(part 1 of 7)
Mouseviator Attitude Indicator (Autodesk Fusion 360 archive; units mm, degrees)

design "Mouseviator Attitude Indicator" references "Bezel BOXY LED and Glass MS33638C", "G1000/Steam C172 Panel Sketch", "Bezel LED and Glass MS33638C", "ULN2003 Stepper Driver v18", "Hall Effect Sensor SS494B", "microswitch 10T85", "28BYJ-48"
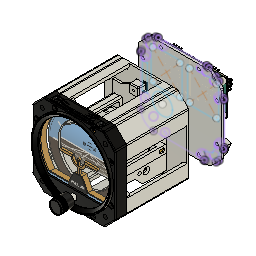
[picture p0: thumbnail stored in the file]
parameter "User Parameter" = 0 (= "Real is 85 but the way I did this makes it impractical")
parameter "MagRollDim" = 32
parameter "MagPitchDim" = 22
parameter "d63" = 5
parameter "d519" = 3
canvas "Canvas1"
canvas "Canvas2"
canvas "Canvas1" bodies "Standard Bezel"
canvas "Canvas1" bodies "Body1"
external_derived "Instrument Sketch" bodies "Body1", "Body2", "Standard Bezel", "Seal", "Top LED Holder"
derived_instance "DerivedInstance1"
joint "Assemble1"
derived_instance "DerivedInstance1"
derived_instance "DerivedInstance2"
derived_instance "DerivedInstance3"
derived_instance "DerivedInstance4"
derived_instance "DerivedInstance5"
derived_instance "DerivedInstance1"
derived_instance "DerivedInstance2"
external_derived "ExternalDerived1" bodies "Standard Bezel (1)"
move "Move3"
extrude "Extrude4" add of existing geometry to an object bodies "Standard Bezel"
delete_face "DeleteFace1"
delete_face "DeleteFace2"
sketch "Sketch1" plane through (0, -8.25, 0) normal (0, -1, 0) x axis (1, 0, 0)
  line L1 (46.051, -23.75) -> (-31.7968, -23.75)
  line L2 (29.1716, -41.2776) -> (-29.1716, -41.2776)
  arc A1 centre (36.96, 18.76) radius 2.5 clockwise from (34.5701, 19.4937) to (36.1415, 16.3978)
  arc A2 centre (0, 0) radius 39.6875 clockwise from (-34.4065, -19.781) to (-34.5701, -19.4937)
  arc A3 centre (36.96, -18.76) radius 2.5 clockwise from (36.1415, -16.3978) to (34.5701, -19.4937)
  arc A4 centre (0, 0) radius 39.6875 clockwise from (34.5701, -19.4937) to (34.4065, -19.781)
  arc A5 centre (18.76, -36.96) radius 2.5 clockwise from (19.4937, -34.5701) to (16.3978, -36.1415)
  arc A6 centre (0, 0) radius 39.6875 clockwise from (16.3978, -36.1415) to (16.0962, -36.2769)
  arc A7 centre (-18.76, -36.96) radius 2.5 clockwise from (-16.3978, -36.1415) to (-19.4937, -34.5701)
  arc A8 centre (0, 0) radius 39.6875 clockwise from (-19.4937, -34.5701) to (-19.781, -34.4065)
  arc A9 centre (-36.96, -18.76) radius 2.5 clockwise from (-34.5701, -19.4937) to (-36.1415, -16.3978)
  arc A10 centre (0, 0) radius 39.6875 clockwise from (-36.1415, -16.3978) to (-36.2769, -16.0962)
  arc A11 centre (-36.96, 18.76) radius 2.5 clockwise from (-36.1415, 16.3978) to (-34.5701, 19.4937)
  arc A12 centre (0, 0) radius 39.6875 clockwise from (-34.5701, 19.4937) to (-34.4065, 19.781)
  arc A13 centre (-18.76, 36.96) radius 2.5 clockwise from (-19.4937, 34.5701) to (-16.3978, 36.1415)
  arc A14 centre (0, 0) radius 39.6875 clockwise from (-16.3978, 36.1415) to (-16.0962, 36.2769)
  arc A15 centre (18.76, 36.96) radius 2.5 clockwise from (16.3978, 36.1415) to (19.4937, 34.5701)
  arc A16 centre (0, 0) radius 39.6875 clockwise from (19.4937, 34.5701) to (19.781, 34.4065)
  circle C1 centre (0, -29.75) radius 3
  arc A17 centre (0, 0) radius 39.6875 clockwise from (-16.3978, -36.1415) to (-19.4937, -34.5701)
  arc A18 centre (0, 0) radius 39.6875 clockwise from (19.4937, -34.5701) to (16.3978, -36.1415)
  arc A19 centre (-36.96, -18.76) radius 2.75 clockwise from (-34.4065, -19.781) to (-36.2769, -16.0962)
  arc A20 centre (36.96, -18.76) radius 2.75 clockwise from (36.2769, -16.0962) to (34.4065, -19.781)
  arc A21 centre (0, 0) radius 39.6875 clockwise from (36.2769, -16.0962) to (36.1415, -16.3978)
  arc A22 centre (18.76, -36.96) radius 2.75 clockwise from (19.781, -34.4065) to (16.0962, -36.2769)
  arc A23 centre (0, 0) radius 39.6875 clockwise from (19.781, -34.4065) to (19.4937, -34.5701)
  arc A24 centre (-18.76, -36.96) radius 2.75 clockwise from (-16.0962, -36.2769) to (-19.781, -34.4065)
  arc A25 centre (0, 0) radius 39.6875 clockwise from (-16.0962, -36.2769) to (-16.3978, -36.1415)
  arc A26 centre (-18.76, 36.96) radius 2.75 clockwise from (-19.781, 34.4065) to (-16.0962, 36.2769)
  arc A27 centre (0, 0) radius 39.6875 clockwise from (-19.781, 34.4065) to (-19.4937, 34.5701)
  arc A28 centre (-36.96, 18.76) radius 2.75 clockwise from (-36.2769, 16.0962) to (-34.4065, 19.781)
  arc A29 centre (0, 0) radius 39.6875 clockwise from (-36.2769, 16.0962) to (-36.1415, 16.3978)
  arc A30 centre (36.96, 18.76) radius 2.75 clockwise from (34.4065, 19.781) to (36.2769, 16.0962)
  arc A31 centre (0, 0) radius 39.6875 clockwise from (34.4065, 19.781) to (34.5701, 19.4937)
  arc A32 centre (0, 0) radius 39.6875 clockwise from (36.1415, 16.3978) to (36.2769, 16.0962)
  arc A33 centre (18.76, 36.96) radius 2.75 clockwise from (16.0962, 36.2769) to (19.781, 34.4065)
  arc A34 centre (0, 0) radius 39.6875 clockwise from (16.0962, 36.2769) to (16.3978, 36.1415)
  circle C2 centre (0, 0) radius 35.6721
  point P27 (-31.7968, -23.75)
  point P1 (0, 0)
  point P29 (0, -29.75)
  coincident A8 P27
  horizontal L1
  vertical P1 P29
  dimension "d1" distance P1 L1 = 23.75
  dimension "d2" diameter C1 = 6
  dimension "d3" distance L1 P29 = 6
extrude "Extrude1" add sketch "Sketch1" profile of L1 C1 C2 against normal blind 10.25 and against normal blind 0
work_plane "WorkPlane1" AlongDistance 60
sketch "Backing Plate" plane through (0, 62, 0) normal (0, 1, 0) x axis (1, 0, 0)
  line L1 (-1.5, 41.2776) -> (1.5, 41.2776)
  line L2 (-15, 0) -> (0, 0)
  line L3 (0, -15) -> (0, 0)
  line L4 (0, -15) -> (0, -22.5)
  line L5 (0, 15) -> (0, 22.5)
  line L6 (13.3564, 0) -> (0, 0)
  line L7 (-26.748, -34.183) -> (-33.4655, -27.4655)
  line L8 (-25.7359, -27.4655) -> (-33.4655, -27.4655)
  line L9 (-40.6918, 30.5858) -> (-30.5858, 40.6918)
  line L10 (-41.2776, -29.1716) -> (-41.2776, 29.1716)
  line L11 (-30.5858, -40.6918) -> (-40.6918, -30.5858)
  line L12 (-25.502, -41.2776) -> (-29.1716, -41.2776)
  line L13 (24.1231, -41.4655) -> (-24.1331, -41.4655)
  line L14 (29.1716, -41.2776) -> (25.492, -41.2776)
  line L15 (40.6918, -30.5858) -> (30.5858, -40.6918)
  line L16 (41.2776, 29.1716) -> (41.2776, -29.1716)
  line L17 (30.5858, 40.6918) -> (40.6918, 30.5858)
  line L18 (1.5, 41.2776) -> (29.1716, 41.2776)
  line L19 (1.5, 39.6216) -> (1.5, 41.2776)
  line L20 (-1.5, 41.2776) -> (-1.5, 39.6216)
  line L21 (-29.1716, 41.2776) -> (-1.5, 41.2776)
  line L22 (-15, 8.75) -> (-22.5, 8.75)
  line L23 (-15, -8.75) -> (-15, 8.75)
  line L24 (-22.5, -8.75) -> (-15, -8.75)
  line L25 (-22.5, 8.75) -> (-22.5, -8.75)
  line L26 (-15, -8.75) -> (-22.5, 8.75)
  line L27 (-22.5, -8.75) -> (-15, 8.75)
  line L28 (-15, 0) -> (-22.5, 0)
  line L29 (2.325, -29.875) -> (-2.325, -29.875)
  line L30 (2.325, -34.125) -> (2.325, -29.875)
  line L31 (-2.325, -34.125) -> (2.325, -34.125)
  line L32 (-2.325, -29.875) -> (-2.325, -34.125)
  line L33 (2.325, -34.125) -> (-2.325, -29.875)
  line L34 (-2.325, -34.125) -> (2.325, -29.875)
  line L35 (-2.3746, -28.5229) -> (-2.325, -29.875)
  line L36 (2.325, -29.875) -> (2.3746, -28.5229)
  line L37 (1.75, -27.875) -> (-1.75, -27.875)
  line L38 (-1.75, -29.125) -> (1.75, -29.125)
  circle C1 centre (0, 0) radius 5
  arc A1 centre (0, 0) radius 15 clockwise from (0, -15) to (-15, 0)
  arc A2 centre (0, 0) radius 22.5 clockwise from (0, -22.5) to (-22.5, 0)
  arc A3 centre (0, 0) radius 22.5 clockwise from (-22.5, 0) to (0, 22.5)
  arc A4 centre (0, 0) radius 15 clockwise from (-15, 0) to (0, 15)
  circle C2 centre (-33.4655, -27.4655) radius 1.4
  circle C3 centre (-26.748, -34.183) radius 1.4
  circle C4 centre (-31.4309, 31.4309) radius 2.159
  circle C5 centre (-31.4309, -31.4309) radius 2.159
  circle C6 centre (31.4309, 31.4309) radius 2.159
  circle C7 centre (31.4309, -31.4309) radius 2.159
  circle C8 centre (18.76, -36.96) radius 1.4
  circle C9 centre (36.96, 18.76) radius 1.4
  circle C10 centre (-18.76, 36.96) radius 1.4
  circle C11 centre (-36.96, -18.76) radius 1.4
  circle C12 centre (-18.76, -36.96) radius 1.4
  circle C13 centre (-36.96, 18.76) radius 1.4
  circle C14 centre (18.76, 36.96) radius 1.4
  circle C15 centre (36.96, -18.76) radius 1.4
  arc A5 centre (-39.2776, 29.1716) radius 2 clockwise from (-41.2776, 29.1716) to (-40.6918, 30.5858)
  arc A6 centre (-39.2776, -29.1716) radius 2 clockwise from (-40.6918, -30.5858) to (-41.2776, -29.1716)
  arc A7 centre (-29.1716, -39.2776) radius 2 clockwise from (-29.1716, -41.2776) to (-30.5858, -40.6918)
  arc A8 centre (-24.1331, -36.3855) radius 5.08 clockwise from (-24.1331, -41.4655) to (-25.502, -41.2776)
  arc A9 centre (24.1231, -36.3855) radius 5.08 clockwise from (25.492, -41.2776) to (24.1231, -41.4655)
  arc A10 centre (29.1716, -39.2776) radius 2 clockwise from (30.5858, -40.6918) to (29.1716, -41.2776)
  arc A11 centre (39.2776, -29.1716) radius 2 clockwise from (41.2776, -29.1716) to (40.6918, -30.5858)
  arc A12 centre (39.2776, 29.1716) radius 2 clockwise from (40.6918, 30.5858) to (41.2776, 29.1716)
  arc A13 centre (29.1716, 39.2776) radius 2 clockwise from (29.1716, 41.2776) to (30.5858, 40.6918)
  arc A14 centre (0, 0) radius 39.65 clockwise from (1.5, 39.6216) to (-1.5, 39.6216)
  arc A15 centre (-29.1716, 39.2776) radius 2 clockwise from (-30.5858, 40.6918) to (-29.1716, 41.2776)
  circle C16 centre (0, -28.5) radius 0.625
  circle C17 centre (-1.75, -28.5) radius 0.625
  circle C18 centre (1.75, -28.5) radius 0.625
  point P5 (0, -15)
  point P11 (0, 15)
  point P7 (0, -22.5)
  point P10 (0, 22.5)
  point P8 (0, 0)
  point P13 (0, 0)
  point P15 (-33.4655, -27.4655)
  point P17 (-33.4655, -27.4655)
  point P16 (-26.748, -34.183)
  point P18 (-26.748, -34.183)
  point P65 (1.5, 41.2776)
  point P75 (1.5, 41.2776)
  point P71 (-1.5, 41.2776)
  point P76 (-1.5, 41.2776)
  point P81 (-18.75, 0)
  point P2 (0, 0)
  point P12 (0, 0)
  point P1 (0, 0)
  point P86 (0, -32)
  point P87 (0, -28.5)
  point P90 (-2.3746, -28.5229)
  point P91 (2.3746, -28.5229)
  point P92 (-1.75, -27.875)
  point P93 (1.75, -27.875)
  point P94 (1.75, -29.125)
  point P95 (-1.75, -29.125)
  point P79 (-15, -8.75)
  point P80 (-22.5, -8.75)
  point P78 (-15, 8.75)
  point P6 (0, 0)
  point P83 (2.325, -29.875)
  point P84 (2.325, -34.125)
  point P82 (-2.325, -29.875)
  parallel L3 L4
  symmetric P5 L2 P11
  symmetric A1 L2 A4
  symmetric L2 P7 P10
  symmetric L2 A2 A3
  coincident P8 P13
  horizontal L6
  horizontal L8
  coincident P15 P17
  coincident P16 P18
  coincident P65 P75
  coincident P71 P76
  horizontal L22
  perpendicular L22 L23
  parallel L22 L24
  parallel L23 L25
  coincident L26 P81
  coincident L27 P81
  parallel L2 L28
  midpoint P81 L28
  coincident P2 P12
  coincident P1 P8
  horizontal L29
  perpendicular L29 L30
  parallel L29 L31
  parallel L30 L32
  coincident L33 P86
  coincident L34 P86
  vertical P8 P86
  vertical P86 P87
  coincident C17 P90
  tangent C17 L35
  coincident C18 P91
  tangent C18 L36
  coincident C17 P92
  coincident C18 P93
  tangent C18 L37
  coincident C18 P94
  coincident C17 P95
  tangent C17 L38
  dimension "d9" diameter C1 = 10
  dimension "d92" angle L2 L3 = 90
  dimension "d93" radius A1 = 15
  dimension "d94" = 7.5
  dimension "d95" angle L2 L6 = 180
  dimension "d182" diameter C2 = 2.8
  dimension "d183" diameter C3 = 2.8 (= "d182")
  dimension "d184" angle L7 L8 = 45
  dimension "d185" distance P17 P18 = 9.5
  dimension "d363" distance P79 P80 = 7.5
  dimension "d364" distance P78 P79 = 17.5
  dimension "d437" distance P6 P86 = 32 (= "MagRollDim")
  dimension "d438" distance P83 P84 = 4.25
  dimension "d439" distance P82 P83 = 4.65
  dimension "d442" distance P86 P87 = 3.5
  dimension "d443" diameter C16 = 1.25
  dimension "d446" R-Pattern1-uDistance = 1.75
  dimension "d447" R-Pattern1-vDistance = 0
extrude "Extrude1" new body sketch "Backing Plate" profile of L1 C1 A1 A2 L4 A3 L5 A4 C2 C3 L7 C4 C5 C6 C7 C8 C9 C10 C11 C12 C13 C14 C15 L9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 along normal blind 2
component_insert "Component Insert1"
joint "Assemble1" alignAngle 0 alignOffsetX 0 alignOffsetY 0 alignOffsetZ 0
work_plane "WorkPlane1" AlongDistance -1.5
sketch "Square with wall profiles" plane through (0, 55.28, 0) normal (0, -1, 0) x axis (1, 0, 0)
  line L1 (23, -27) -> (23, 27)
  line L2 (26, -27) -> (26, 27)
  line L3 (-26, 27) -> (26, 27)
  line L4 (-26, -27) -> (-26, 27)
  line L5 (26, -27) -> (-26, -27)
  line L6 (26, 27) -> (26, -27)
  line L7 (-26, -27) -> (26, 27)
  line L8 (26, -27) -> (-26, 27)
  line L9 (0, 16.6092) -> (0, 0)
  line L10 (-23, -27) -> (-23, 27)
  line L11 (-23, 14.5) -> (-26, 14.5)
  line L12 (-23, -14.5) -> (-26, -14.5)
  line L13 (-21.5, -9) -> (-13.5, -9)
  line L14 (-21.5, 9) -> (-21.5, -9)
  line L15 (-13.5, 9) -> (-21.5, 9)
  line L16 (-13.5, -9) -> (-13.5, 9)
  line L17 (-21.5, 9) -> (-13.5, -9)
  line L18 (-13.5, 9) -> (-21.5, -9)
  line L19 (-1.6591, 1.46) -> (1.6591, 1.46)
  line L20 (1.6591, -1.46) -> (-1.6591, -1.46)
  line L21 (-1.7896, 1.76) -> (1.7896, 1.76)
  line L22 (1.7896, -1.76) -> (-1.7896, -1.76)
  line L23 (0, 35.4451) -> (-7.5188, 31.1041)
  line L24 (0, 35.4451) -> (7.5188, 31.1041)
  line L25 (2.75, 34.75) -> (-2.75, 34.75)
  line L26 (2.75, 29.25) -> (2.75, 34.75)
  line L27 (-2.75, 29.25) -> (2.75, 29.25)
  line L28 (-2.75, 34.75) -> (-2.75, 29.25)
  line L29 (2.75, 29.25) -> (-2.75, 34.75)
  line L30 (-2.75, 29.25) -> (2.75, 34.75)
  line L31 (-4.75, 27.25) -> (4.75, 27.25)
  line L32 (-4.75, 36.75) -> (-4.75, 27.25)
  line L33 (4.75, 36.75) -> (-4.75, 36.75)
  line L34 (4.75, 27.25) -> (4.75, 36.75)
  arc A1 centre (0, 0) radius 2.21 clockwise from (-1.6591, -1.46) to (-1.6591, 1.46)
  arc A2 centre (0, 0) radius 2.21 clockwise from (1.6591, 1.46) to (1.6591, -1.46)
  arc A3 centre (0, 0) radius 2.51 clockwise from (-1.7896, -1.76) to (-1.7896, 1.76)
  arc A4 centre (0, 0) radius 2.51 clockwise from (1.7896, 1.76) to (1.7896, -1.76)
  circle C1 centre (0, 0) radius 32
  circle C2 centre (0, 0) radius 6.25
  circle C3 centre (0, 32) radius 1
  point P8 (0, 0)
  point P4 (26, 27)
  point P2 (23, 27)
  point P1 (0, 0)
  point P9 (0, 0)
  point P11 (-23, 27)
  point P3 (23, -27)
  point P12 (-23, -27)
  point P13 (-26, 14.5)
  point P14 (-23, 14.5)
  point P15 (-26, -14.5)
  point P16 (-23, -14.5)
  point P21 (-17.5, 0)
  point P34 (-7.5188, 31.1041)
  point P33 (0, 0)
  point P35 (0, 35.4451)
  point P36 (7.5188, 31.1041)
  point P37 (0, 35.4451)
  point P43 (0, 32)
  point P48 (0, 32)
  point P7 (26, -27)
  point P19 (-21.5, 9)
  point P20 (-13.5, 9)
  point P18 (-21.5, -9)
  point P41 (2.75, 29.25)
  point P42 (-2.75, 29.25)
  point P40 (2.75, 34.75)
  vertical L1
  parallel L1 L2
  horizontal L3
  perpendicular L3 L4
  parallel L3 L5
  parallel L4 L6
  coincident L7 P8
  coincident L8 P8
  coincident L2 P4
  coincident P2 L3
  coincident P1 P8
  coincident P8 P9
  perpendicular L3 L9
  symmetric P2 L9 P11
  symmetric P3 L9 P12
  coincident L4 P13
  coincident L10 P14
  perpendicular L10 L11
  coincident L4 P15
  coincident L10 P16
  perpendicular L10 L12
  horizontal L13
  perpendicular L13 L14
  parallel L13 L15
  parallel L14 L16
  coincident L17 P21
  coincident L18 P21
  concentric A1 C1
  coincident C1 P34
  vertical P33 P35
  symmetric L9 P34 P36
  symmetric L9 P35 P37
  horizontal P21 P33
  concentric C1 C2
  coincident P3 L5
  horizontal L25
  perpendicular L25 L26
  parallel L25 L27
  parallel L26 L28
  coincident L29 P43
  coincident L30 P43
  coincident L9 P43
  coincident P43 P48
  dimension "d22" distance L1 L2 = 3
  dimension "d60" distance P1 L1 = 23
  dimension "d64" distance P4 P7 = 54
  dimension "d86" distance L3 L11 = 12.5
  dimension "d87" distance L5 L12 = 12.5 (= "d86")
  dimension "d90" distance P19 P20 = 8
  dimension "d91" distance P18 P19 = 18
  dimension "d96" distance P8 P21 = 17.5
  dimension "d171" = 0.3
  dimension "d176" diameter C1 = 64
  dimension "d177" angle L3 L23 = 30
  dimension "d373" diameter C2 = 12.5
  dimension "d425" distance P41 P42 = 5.5
  dimension "d426" distance P40 P41 = 5.5
  dimension "d427" distance P33 P43 = 32 (= "MagRollDim")
  dimension "d428" = -2
  dimension "d511" diameter C3 = 2
extrude "Extrude1" new body sketch "Square with wall profiles" profile of L1 L2 L3 L4 L5 L6 L10 L11 L12 L13 L14 L15 L16 A4 L21 A3 L22 C1 C2 L25 L26 L27 L28 L31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 against normal blind 2
extrude "Extrude13" add sketch "Square with wall profiles" profile of C1 L25 L26 L27 L28 L31 L32 L33 L34 along normal blind 3
extrude "Extrude14" sketch "Square with wall profiles" profile of C1 L25 L26 L27 L28 L31 L32 L33 L34 C3 blind 2
extrude "Extrude11" add sketch "Square with wall profiles" profile of A4 L21 A3 L22 C2 against normal blind 5
extrude "Extrude2" add sketch "Square with wall profiles" profile of L1 L2 L3 L5 L6 C1 along normal blind 30
sketch "Stepper and Microswitch mounting" plane through (23, 0, 0) normal (-1, 0, 0) x axis (0, -1, 0)
  line L1 (-25.28, 27) -> (-25.28, -27)
  line L2 (-55.28, -27) -> (-55.28, 27)
  line L3 (-55.28, 27) -> (-25.28, 27)
  line L4 (-35.1539, 6.3901) -> (-44.28, 0)
  line L5 (-43.6816, -0.8547) -> (-44.28, 0)
  line L6 (-27.6437, 0) -> (-44.28, 0)
  line L7 (-44.9981, 20.449) -> (-35.1539, 6.3901)
  line L8 (-52.78, 15) -> (-44.9981, 20.449)
  line L9 (-25.28, -27) -> (-55.28, -27)
  line L10 (-46.2143, 5.3599) -> (-32.6739, 14.8409)
  line L11 (-55.28, -27) -> (-55.28, 27)
  circle C1 centre (-44.28, 0) radius 5
  circle C2 centre (-44.9981, 20.449) radius 1.4
  circle C3 centre (-52.78, 15) radius 1.4
  circle C4 centre (-44.9981, -20.449) radius 1.4
  circle C5 centre (-52.78, -15) radius 1.4
  circle C6 centre (-48.889, 17.7245) radius 1.6
  circle C7 centre (-48.889, -17.7245) radius 1.6
  circle C8 centre (-30.1171, 16.6312) radius 1.6
  circle C9 centre (-30.1171, -16.6312) radius 1.6
  point P5 (-44.28, 0)
  point P6 (-55.28, 0)
  point P9 (-44.28, 0)
  point P11 (-44.28, 0)
  point P14 (-44.9981, 20.449)
  point P15 (-44.9981, 20.449)
  point P16 (-44.9981, 20.449)
  point P17 (-52.78, 15)
  point P18 (-52.78, 15)
  point P22 (-48.889, 17.7245)
  point P26 (-30.1171, 16.6312)
  point P10 (-35.1539, 6.3901)
  horizontal P5 P6
  coincident P5 P9
  coincident P5 P11
  perpendicular L4 L5
  horizontal L6
  perpendicular L4 L7
  coincident P14 P15
  coincident P15 P16
  perpendicular L7 L8
  coincident P17 P18
  equal C2 C3
  symmetric L6 C2 C4
  symmetric L6 C3 C5
  midpoint L8 P22
  symmetric L6 C6 C7
  perpendicular L7 L10
  coincident L10 P26
  symmetric L6 C8 C9
  dimension "d19" diameter C1 = 10
  dimension "d27" distance P5 L2 = 11
  dimension "d111" angle L4 L6 = 35 (= "PitchTravelDeg / 2")
  dimension "d118" distance P10 P14 = 17.1627
  dimension "d119" distance P9 P10 = 11.1409
  dimension "d121" diameter C2 = 2.8
  dimension "d122" distance P16 P17 = 9.5
  dimension "d386" distance P5 P18 = 15
  dimension "d387" distance P6 P18 = 2.5
  dimension "d420" diameter C6 = 3.2
  dimension "d421" diameter C8 = 3.2
  dimension "d422" distance L4 L10 = 5.5
  dimension "d424" distance L7 P26 = 10
extrude "Extrude3" cut sketch "Stepper and Microswitch mounting" profile of C1 C8 C9 to an object
component_insert "Component Insert2"
joint "Assemble2" alignAngle 90 alignOffsetX 0 alignOffsetY 0 alignOffsetZ 0
work_plane "WorkPlane1" AlongDistance 1
sketch "Right Arm" plane through (34.12, 54.78, 0) normal (1, 0, 0) x axis (0, 1, 0)
  line L1 (-47.5, -4) -> (-5.5, -4)
  line L2 (-47.5, 4) -> (-47.5, -4)
  line L3 (-5.5, 4) -> (-47.5, 4)
  line L4 (-5.5, -4) -> (-5.5, 4)
  line L5 (-47.5, 4) -> (-5.5, -4)
  line L6 (-5.5, 4) -> (-47.5, -4)
  line L7 (-8.8409, -1.46) -> (-12.1591, -1.46)
  line L8 (-12.1591, 1.46) -> (-8.8409, 1.46)
  line L9 (-8.7104, -1.76) -> (-12.2896, -1.76)
  line L10 (-12.2896, 1.76) -> (-8.7104, 1.76)
  arc A1 centre (-10.5, 0) radius 2.21 clockwise from (-8.8409, 1.46) to (-8.8409, -1.46)
  arc A2 centre (-10.5, 0) radius 2.21 clockwise from (-12.1591, -1.46) to (-12.1591, 1.46)
  circle C1 centre (-10.5, 0) radius 5
  arc A3 centre (-10.5, 0) radius 2.51 clockwise from (-8.7104, 1.76) to (-8.7104, -1.76)
  arc A4 centre (-10.5, 0) radius 2.51 clockwise from (-12.2896, -1.76) to (-12.2896, 1.76)
  point P6 (-26.5, 0)
  point P1 (0, 0)
  point P4 (-47.5, 4)
  point P5 (-5.5, 4)
  point P10 (-10.5, 0)
  point P2 (-5.5, -4)
  horizontal L1
  perpendicular L1 L2
  parallel L1 L3
  parallel L2 L4
  coincident L5 P6
  coincident L6 P6
  midpoint L6 P6
  horizontal P1 P6
  concentric A1 C1
  dimension "d61" distance P4 P5 = 42
  dimension "d160" distance L4 P10 = 5
  dimension "d161" distance P2 P5 = 8
  dimension "d392" = 0.3
  dimension "d423" diameter C1 = 10
extrude "Extrude1" new body sketch "Right Arm" profile of L1 L2 L3 L4 C1 L9 A4 L10 A3 against normal blind 2.5
mirror "Mirror1" mirrorStitchTolerance 0.1
work_axis "WorkAxis1"
work_plane "WorkPlane2" AlongDistance 0
sketch "Sketch2" plane through (0, 0, 0) normal (1, 0, 0) x axis (0, 1, 0)
  line L1 (7.28, 4) -> (7.28, -4)
  line L2 (14.9269, 20.8421) -> (13.2961, 22)
  line L3 (8.28, 0) -> (6.28, 0)
  line L4 (14.9269, -20.8421) -> (13.2961, -22)
  line L5 (57.28, 31.6455) -> (57.28, 27)
  line L6 (57.28, 31.6455) -> (57.28, 27)
  arc A1 centre (44.28, 0) radius 38 clockwise from (6.28, 0) to (13.2961, 22)
  arc A2 centre (44.28, 0) radius 36 clockwise from (8.28, 0) to (14.9269, 20.8421)
  arc A3 centre (44.28, 0) radius 38 clockwise from (13.2961, -22) to (6.28, 0)
  arc A4 centre (44.28, 0) radius 36 clockwise from (14.9269, -20.8421) to (8.28, 0)
  point P2 (44.28, 0)
  point P4 (6.28, 0)
  point P1 (0, 0)
  point P3 (13.2961, 22)
  point P11 (13.2961, -22)
  point P12 (6.28, 0)
  point P8 (8.28, 0)
  point P15 (8.28, 0)
  point P9 (14.9269, 20.8421)
  point P13 (14.9269, -20.8421)
  point P14 (44.28, 0)
  point P16 (44.28, 0)
  point P6 (7.28, 4)
  horizontal P2 P4
  horizontal P1 P4
  perpendicular L1 L3
  symmetric P3 L3 P11
  symmetric P4 L3 P12
  symmetric A1 L3 A3
  symmetric P8 L3 P15
  symmetric P9 L3 P13
  symmetric A2 L3 A4
  coincident P14 P16
  dimension "d38" = -2
  dimension "d140" distance P3 P6 = 18
  dimension "d141" distance L1 P15 = 1
extrude "Extrude2" add sketch "Sketch2" profile of A1 A2 L2 A3 L4 A4 distance 32.5
work_plane "WorkPlane1" AlongDistance 0.5
sketch "Sketch1" plane through (0, 2.5, 0) normal (0, 1, 0) x axis (1, 0, 0)
  circle C1 centre (0, 0) radius 37.25
  circle C2 centre (0, 0) radius 27.6721
  circle C3 centre (0, 0) radius 35.6721
  point P1 (0, 0)
  point P2 (0, 0)
  point P3 (0, 0)
  coincident P1 P2
  coincident P1 P3
  dimension "d504" diameter C1 = 74.5
  dimension "d528" distance C2 C3 = 8
extrude "Extrude1" new body sketch "Sketch1" profile of C1 C2 along normal blind 2
sketch "Sketch3" plane through (0, 0, 0) normal (0, 1, 0) x axis (-1, 0, 0)
  curve K1 (32.5, 0) -> (-32.5, 0)
  curve K2 (0, 17.7833) -> (0, -17.7833)
  line L1 (32.5, 22) -> (-32.5, 22)
  line L2 (-32.5, -22) -> (32.5, -22)
  line L3 (-32.5, -22) -> (-32.5, 22)
  line L4 (32.5, 22) -> (-32.5, 22)
  line L5 (32.5, 22) -> (32.5, -22)
  line L6 (34.12, 4) -> (34.12, -4)
  line L7 (31.62, 4) -> (34.12, 4)
  line L8 (31.62, -4) -> (31.62, 4)
  line L9 (34.12, -4) -> (31.62, -4)
  line L10 (-34.12, -4) -> (-34.12, 4)
  line L11 (-31.62, -4) -> (-34.12, -4)
  line L12 (-31.62, 4) -> (-31.62, -4)
  line L13 (-34.12, 4) -> (-31.62, 4)
  closed curve K3 centre (0, 0)
  point P3 (-32.5, 0)
  point P4 (32.5, 0)
  point P5 (0, -17.7833)
  point P6 (0, 17.7833)
  point P2 (0, 0)
  point P7 (0, 0)
  coincident K3 P3
  coincident K3 P4
  coincident K3 P5
  coincident K3 P6
  horizontal K1
  coincident P2 P7
extrude "Extrude3" cut sketch "Sketch3" profile of K3 L1 L2 L3 L4 L5 L7 L9 L11 L13 along normal blind 20
sketch "Sketch3" plane through (0, 0, 0) normal (1, 0, 0) x axis (0, 1, 0)
  line L1 (22.8033, 27) -> (24.0483, 25.4348)
  line L2 (42.7383, 0) -> (44.28, 0)
  line L3 (28.8507, 0) -> (42.7383, 0)
  line L4 (22.8033, -27) -> (24.0483, -25.4348)
  arc A1 centre (44.28, 0) radius 34.5 clockwise from (9.78, 0) to (22.8033, 27)
  arc A2 centre (44.28, 0) radius 32.5 clockwise from (11.78, 0) to (24.0483, 25.4348)
  arc A3 centre (44.28, 0) radius 38 clockwise from (6.4911, -4) to (6.4911, 4)
  arc A4 centre (44.28, 0) radius 34.5 clockwise from (22.8033, -27) to (9.78, 0)
  arc A5 centre (44.28, 0) radius 32.5 clockwise from (24.0483, -25.4348) to (11.78, 0)
  point P1 (0, 0)
  point P4 (9.78, 0)
  point P2 (44.28, 0)
  point P15 (6.28, 0)
  point P8 (44.28, 0)
  point P16 (44.28, 0)
  point P3 (22.8033, 27)
  point P20 (22.8033, -27)
  point P21 (9.78, 0)
  point P6 (24.0483, 25.4348)
  point P22 (24.0483, -25.4348)
  point P7 (11.78, 0)
  point P24 (11.78, 0)
  horizontal P1 P4
  horizontal P2 P4
  midpoint A3 P15
  coincident P2 P8
  coincident P2 P16
  horizontal L2
  parallel L2 L3
  symmetric P3 L3 P20
  symmetric P4 L3 P21
  symmetric A1 L3 A4
  symmetric P6 L3 P22
  symmetric A2 L3 A5
  symmetric P7 L3 P24
  dimension "d53" = -2
  dimension "d68" distance P1 P3 = 27
  dimension "d331" distance P4 P15 = 3.5 (= "2 mm + 1.5 mm")
extrude "Extrude4" new body sketch "Sketch3" profile of A1 A2 L1 distance 30
sketch "Sketch4" plane through (-3.75, 0, 0) normal (0, 1, 0) x axis (1, 0, 0)
  line L1 (33.75, 27) -> (33.75, -27)
  line L2 (-26.25, -27) -> (33.75, -27)
  line L3 (-26.25, -27) -> (-26.25, 27)
  curve K1 (33.75, 0) -> (-26.25, 0)
  curve K2 (3.75, 27) -> (3.75, -27)
  line L4 (33.75, 27) -> (-26.25, 27)
  closed curve K3 centre (3.75, 0)
  point P8 (-26.25, 0)
  point P9 (33.75, 0)
  point P10 (3.75, -27)
  point P11 (3.75, 27)
  point P6 (3.75, 0)
  point P7 (3.75, 0)
  coincident K3 P8
  coincident K3 P9
  coincident K3 P10
  coincident K3 P11
  coincident P6 P7
  perpendicular L1 K1
  coincident L2 P10
extrude "Extrude5" cut sketch "Sketch4" profile of L1 L2 L3 K3 along normal blind 50
as_built_joint "As-built1" OffsetX 0 OffsetY 0 OffsetZ 0 AngleZ 0 AngleMinimum -35 (= "-( PitchTravelDeg / 2 )") AngleMaximum 35 (= "( PitchTravelDeg / 2 )")
as_built_joint "As-built1" OffsetX 0 OffsetY 0 OffsetZ 0 AngleZ 0 AngleMinimum -180 AngleMaximum 180 RotateRest 0
ground "Ground1"
sketch "Sketch5" plane through (0, 25.28, 0) normal (0, -1, 0) x axis (1, 0, 0)
  line L1 (26, 27) -> (26, -27)
  line L2 (23, 27) -> (26, 27)
  line L3 (23, -27) -> (23, 27)
  line L4 (26, -27) -> (23, -27)
  line L5 (26, 19) -> (23, 19)
  line L6 (26, -19) -> (23, -19)
  point P6 (23, 19)
  point P7 (26, 19)
  point P8 (23, -19)
  point P9 (26, -19)
  coincident L3 P6
  coincident L1 P7
  perpendicular L1 L5
  coincident L3 P8
  coincident L1 P9
  perpendicular L1 L6
  dimension "d145" distance L4 L6 = 8 (= "d146")
  dimension "d146" distance L2 L5 = 8
extrude "Extrude6" add sketch "Sketch5" profile of L1 L3 L5 L6 to an object
extrude "Extrude7" add sketch "Square with wall profiles" profile of L4 L10 L11 L12 to an object
sketch "Left Arm" plane through (-34.12, 0, 0) normal (-1, 0, 0) x axis (0, -1, 0)
  line L1 (-49.28, 4) -> (-7.28, 4)
  line L2 (-49.28, -4) -> (-49.28, 4)
  line L3 (-7.28, -4) -> (-49.28, -4)
  line L4 (-7.28, 4) -> (-7.28, -4)
  circle C1 centre (-44.28, 0) radius 1.5
  point P6 (-44.28, 0)
  point P7 (-44.28, 0)
  coincident P6 P7
  dimension "d97" diameter C1 = 3
extrude "Extrude4" cut sketch "Left Arm" profile of C1 to an object
sketch "Sketch5" plane through (34.12, 0, 0) normal (1, 0, 0) x axis (0, 1, 0)
  line L1 (7.28, 4) -> (49.28, 4)
  line L2 (7.28, -4) -> (7.28, 4)
  line L3 (49.28, -4) -> (7.28, -4)
  line L4 (49.28, 4) -> (49.28, -4)
  line L5 (45.9391, -1.46) -> (42.6209, -1.46)
  line L6 (42.6209, 1.46) -> (45.9391, 1.46)
  line L7 (42.5115, 1.71) -> (46.0485, 1.71)
  line L8 (46.0485, -1.71) -> (42.5115, -1.71)
  arc A1 centre (44.28, 0) radius 2.21 clockwise from (45.9391, 1.46) to (45.9391, -1.46)
  arc A2 centre (44.28, 0) radius 2.21 clockwise from (42.6209, -1.46) to (42.6209, 1.46)
  arc A3 centre (44.28, 0) radius 2.46 clockwise from (42.5115, -1.71) to (42.5115, 1.71)
  arc A4 centre (44.28, 0) radius 2.46 clockwise from (46.0485, 1.71) to (46.0485, -1.71)
  dimension "d102" = 0.25
extrude "Extrude5" cut sketch "Sketch5" profile of A4 L7 A3 L8 to an object
sketch "Sketch1" plane through (0, 2, 0) normal (0, 1, 0) x axis (-1, 0, 0)
  line L1 (-1.35, -41.3) -> (-1.35, -39.627)
  line L2 (1.35, -41.3) -> (-1.35, -41.3)
  line L3 (1.35, -39.627) -> (1.35, -41.3)
  line L4 (-3.543, 32.597) -> (-3.543, 36.4783)
  line L5 (-2.0322, 27.1385) -> (-3.543, 32.597)
  line L6 (-0.9183, 27.1385) -> (-2.0322, 27.1385)
  line L7 (-0.9183, 36.6385) -> (-0.9183, 27.1385)
  line L8 (0, 10.54) -> (0, 0)
  line L9 (3.543, 32.597) -> (3.543, 36.4783)
  line L10 (2.0322, 27.1385) -> (3.543, 32.597)
  line L11 (0.9183, 27.1385) -> (2.0322, 27.1385)
  line L12 (0.9183, 36.6385) -> (0.9183, 27.1385)
  line L13 (-40.6918, 30.5858) -> (-30.5858, 40.6918)
  line L14 (-41.2776, -29.1716) -> (-41.2776, 29.1716)
  line L15 (-30.5858, -40.6918) -> (-40.6918, -30.5858)
  line L16 (-1.5, -41.2776) -> (-29.1716, -41.2776)
  line L17 (-1.5, -39.6216) -> (-1.5, -41.2776)
  line L18 (1.5, -41.2776) -> (1.5, -39.6216)
  line L19 (29.1716, -41.2776) -> (1.5, -41.2776)
  line L20 (40.6918, -30.5858) -> (30.5858, -40.6918)
  line L21 (41.2776, 29.1716) -> (41.2776, -29.1716)
  line L22 (30.5858, 40.6918) -> (40.6918, 30.5858)
  line L23 (25.502, 41.2776) -> (29.1716, 41.2776)
  line L24 (-24.1231, 41.4655) -> (24.1331, 41.4655)
  line L25 (-29.1716, 41.2776) -> (-25.492, 41.2776)
  circle C1 centre (0, 0) radius 36.65
  arc A1 centre (0, 0) radius 39.65 clockwise from (-1.35, -39.627) to (1.35, -39.627)
  arc A2 centre (-39.2776, 29.1716) radius 2 clockwise from (-41.2776, 29.1716) to (-40.6918, 30.5858)
  arc A3 centre (-39.2776, -29.1716) radius 2 clockwise from (-40.6918, -30.5858) to (-41.2776, -29.1716)
  arc A4 centre (-29.1716, -39.2776) radius 2 clockwise from (-29.1716, -41.2776) to (-30.5858, -40.6918)
  arc A5 centre (0, 0) radius 39.65 clockwise from (-1.5, -39.6216) to (1.5, -39.6216)
  arc A6 centre (29.1716, -39.2776) radius 2 clockwise from (30.5858, -40.6918) to (29.1716, -41.2776)
  arc A7 centre (39.2776, -29.1716) radius 2 clockwise from (41.2776, -29.1716) to (40.6918, -30.5858)
  arc A8 centre (39.2776, 29.1716) radius 2 clockwise from (40.6918, 30.5858) to (41.2776, 29.1716)
  arc A9 centre (29.1716, 39.2776) radius 2 clockwise from (29.1716, 41.2776) to (30.5858, 40.6918)
  arc A10 centre (24.1331, 36.3855) radius 5.08 clockwise from (24.1331, 41.4655) to (25.502, 41.2776)
  arc A11 centre (-24.1231, 36.3855) radius 5.08 clockwise from (-25.492, 41.2776) to (-24.1231, 41.4655)
  arc A12 centre (-29.1716, 39.2776) radius 2 clockwise from (-30.5858, 40.6918) to (-29.1716, 41.2776)
  circle C2 centre (-36.96, 18.76) radius 1.4
  circle C3 centre (-18.76, -36.96) radius 1.4
  circle C4 centre (36.96, -18.76) radius 1.4
  circle C5 centre (18.76, 36.96) radius 1.4
  circle C6 centre (36.96, 18.76) radius 1.4
  circle C7 centre (18.76, -36.96) radius 1.4
  circle C8 centre (-36.96, -18.76) radius 1.4
  circle C9 centre (-18.76, 36.96) radius 1.4
  circle C10 centre (-31.4309, 31.4309) radius 2.159
  circle C11 centre (-31.4309, -31.4309) radius 2.159
  circle C12 centre (31.4309, 31.4309) radius 2.159
  circle C13 centre (31.4309, -31.4309) radius 2.159
  point P7 (-3.543, 36.4783)
  point P11 (-0.9183, 36.6385)
  point P2 (0, 0)
  point P12 (0, 0)
  point P14 (3.543, 36.4783)
  point P8 (-3.543, 32.597)
  point P15 (3.543, 32.597)
  point P9 (-2.0322, 27.1385)
  point P16 (2.0322, 27.1385)
  point P10 (-0.9183, 27.1385)
  point P17 (0.9183, 27.1385)
  point P18 (0.9183, 36.6385)
  coincident C1 P7
  vertical L4
  perpendicular L4 L6
  coincident C1 P11
  perpendicular L6 L7
  coincident P2 P12
  vertical L8
  symmetric P7 L8 P14
  symmetric P8 L8 P15
  symmetric P9 L8 P16
  symmetric P10 L8 P17
  symmetric P11 L8 P18
  dimension "d105" distance P10 P11 = 9.5
extrude "Extrude1" sketch "Sketch1" profile of C1 L4 L5 L6 L7 L9 L10 L11 L12 blind -1.5 from offset -1
component_insert "Component Insert3"
joint "Assemble3" alignAngle 125 (= "90.0 deg + ( PitchTravelDeg / 2 )") alignOffsetX 0 alignOffsetY 0 alignOffsetZ 0
component_insert "Component Insert4"
joint "Assemble4" alignAngle 55 (= "90 deg - PitchTravelDeg / 2") alignOffsetX 0 alignOffsetY 0 alignOffsetZ 0
sketch "Sketch2" plane through (0, 4.5, 0) normal (0, 1, 0) x axis (-1, 0, 0)
  line L1 (-4, 34.25) -> (4, 34.25)
  line L2 (-4, 37.25) -> (-4, 34.25)
  line L3 (4, 37.25) -> (-4, 37.25)
  line L4 (4, 34.25) -> (4, 37.25)
  line L5 (-4, 37.25) -> (4, 34.25)
  line L6 (4, 37.25) -> (-4, 34.25)
  line L7 (-3.75, 37.175) -> (3.75, 37.175)
  line L8 (-3.75, 33.925) -> (-3.75, 37.175)
  line L9 (3.75, 33.925) -> (-3.75, 33.925)
  line L10 (3.75, 37.175) -> (3.75, 33.925)
  line L11 (-3.75, 33.925) -> (3.75, 37.175)
  line L12 (3.75, 33.925) -> (-3.75, 37.175)
  line L13 (4, 37.175) -> (-3.75, 37.175)
  line L14 (4, 37.0346) -> (4, 37.175)
  line L15 (-3.75, 37.0346) -> (4, 37.0346)
  line L16 (-3.75, 37.175) -> (-3.75, 37.0346)
  circle C1 centre (0, 0) radius 27.6721
  circle C2 centre (0, 0) radius 37.25
  point P7 (0, 35.75)
  point P1 (0, 0)
  point P8 (0, 37.25)
  point P13 (0, 35.55)
  point P15 (4, 37.0346)
  point P3 (4, 34.25)
  point P6 (4, 37.25)
  point P4 (-4, 34.25)
  point P11 (-3.75, 33.925)
  point P12 (3.75, 33.925)
  point P9 (3.75, 37.175)
  horizontal L1
  perpendicular L1 L2
  parallel L1 L3
  parallel L2 L4
  coincident L5 P7
  coincident L6 P7
  vertical P1 P7
  midpoint L3 P8
  coincident C2 P8
  horizontal L7
  perpendicular L7 L8
  parallel L7 L9
  parallel L8 L10
  coincident L11 P13
  coincident L12 P13
  vertical P1 P13
  horizontal L13
  vertical L14
  horizontal L15
  vertical L16
  coincident L4 P15
  coincident C2 P15
  dimension "d127" distance P3 P6 = 3
  dimension "d128" distance P3 P4 = 8
  dimension "d129" distance P11 P12 = 7.5
  dimension "d130" distance P9 P12 = 3.25
  dimension "d513" distance P8 L13 = 0.075
extrude "Extrude3" add sketch "Sketch2" profile of C2 L7 L8 L9 L10 L13 L15 L16 to an object
extrude "Extrude2" add sketch "Sketch2" profile of L7 L8 L9 L10 L13 L14 L16 along normal blind 28
work_plane "WorkPlane4" AlongDistance 30
sketch "Sketch6" plane through (-1.5, 25.28, 0) normal (0, -1, 0) x axis (1, 0, 0)
  line L1 (5.25, 20.4348) -> (-2.25, 20.4348)
  line L2 (5.25, 25.4348) -> (5.25, 20.4348)
  line L3 (-2.25, 25.4348) -> (5.25, 25.4348)
  line L4 (-2.25, 20.4348) -> (-2.25, 25.4348)
  line L5 (5.25, 25.4348) -> (-2.25, 20.4348)
  line L6 (-2.25, 25.4348) -> (5.25, 20.4348)
  line L7 (-8.5659, 25.4348) -> (11.5659, 25.4348)
  circle C1 centre (1.5, 22.9348) radius 1.45
  point P6 (1.5, 22.9348)
  point P7 (1.5, 25.4348)
  point P10 (1.5, 22.9348)
  point P5 (-2.25, 25.4348)
  point P2 (-2.25, 20.4348)
  point P3 (5.25, 20.4348)
  horizontal L1
  perpendicular L1 L2
  parallel L1 L3
  parallel L2 L4
  coincident L5 P6
  coincident L6 P6
  coincident P7 L7
  coincident P6 P10
  midpoint P7 L7
  vertical P7 P10
  coincident P5 L7
  dimension "d149" distance P2 P5 = 5
  dimension "d150" distance P2 P3 = 7.5
  dimension "d151" diameter C1 = 2.9
extrude "Extrude9" add sketch "Sketch6" profile of L1 L2 L3 L4 L7 C1 to an object second side blind 1
extrude "Extrude10" cut sketch "Sketch6" profile of C1 no distance stored
hole "Hole1" HoleDepth 10 HoleDiameter 5.5 TipAngle 180
mirror "Mirror1" mirrorStitchTolerance 0.1
sketch "Sketch3" plane through (0, 32.5, 0) normal (0, 1, 0) x axis (-1, 0, 0)
  line L1 (-3.75, 33.925) -> (-3.75, 37.175)
  line L2 (3.75, 33.925) -> (-3.75, 33.925)
  line L3 (3.75, 37.175) -> (3.75, 33.925)
  line L4 (-3.75, 37.175) -> (3.75, 37.175)
  line L5 (-3.75, 20.4348) -> (-3.75, 25.4348)
  line L6 (3.75, 20.4348) -> (-3.75, 20.4348)
  line L7 (3.75, 25.4348) -> (3.75, 20.4348)
  line L8 (3.75, 37.175) -> (-3.75, 37.175)
  line L9 (3.75, 25.4348) -> (3.75, 37.175)
  line L10 (-3.75, 25.4348) -> (3.75, 25.4348)
  line L11 (-3.75, 37.175) -> (-3.75, 25.4348)
  line L12 (-3.75, 25.4348) -> (3.75, 25.4348)
  circle C1 centre (0, 22.9348) radius 1.45
  point P9 (3.75, 25.4348)
  point P12 (3.75, 25.4348)
  point P2 (-3.75, 37.175)
  point P10 (-3.75, 37.175)
  horizontal L8
  vertical L9
  horizontal L10
  vertical L11
  coincident P9 P12
  coincident P2 P10
extrude "Extrude4" add sketch "Sketch3" along normal blind 3
extrude "Extrude5" add sketch "Sketch3" profile of L5 L6 L7 L10 C1 L12 to an object
as_built_joint "As-built2"
fillet "Fillet1" radius 3.5 2 1 1.5
mirror "Mirror1" mirrorStitchTolerance 0.1
decal "Decal1"
component_insert "Component Insert1"
joint "Assemble6" alignAngle 45 alignOffsetX 0 alignOffsetY 0 alignOffsetZ 0
copy_paste "CutPaste"
component_insert "Component Insert6"
joint "Assemble7" alignAngle 185 alignOffsetX -4 alignOffsetY -2 alignOffsetZ 0
extrude "Extrude7" cut sketch "Backing Plate" profile of L29 L30 L31 L32 C16 C17 C18 L35 L36 L37 along normal blind 1
sketch "Lil Microswitch zero nub" plane through (0, 62, 0) normal (0, -1, 0) x axis (1, 0, 0)
  line L1 (0, -38.2776) -> (-7.5, -41.2776)
  line L2 (0, 18.8817) -> (0, -96.0831)
  line L3 (0, -38.2776) -> (7.5, -41.2776)
  line L4 (7.5, -41.2776) -> (-7.5, -41.2776)
  line L5 (40.6918, -30.5858) -> (30.5858, -40.6918)
  line L6 (41.2776, 29.1716) -> (41.2776, -29.1716)
  line L7 (30.5858, 40.6918) -> (40.6918, 30.5858)
  line L8 (25.492, 41.2776) -> (29.1716, 41.2776)
  line L9 (-24.1331, 41.4655) -> (24.1231, 41.4655)
  line L10 (-29.1716, 41.2776) -> (-25.502, 41.2776)
  line L11 (-40.6918, 30.5858) -> (-30.5858, 40.6918)
  line L12 (-41.2776, -29.1716) -> (-41.2776, 29.1716)
  line L13 (-30.5858, -40.6918) -> (-40.6918, -30.5858)
  line L14 (29.1716, -41.2776) -> (-29.1716, -41.2776)
  line L15 (0, 15) -> (0, 22.5)
  line L16 (0, -22.5) -> (0, -15)
  line L17 (-22.5, -8.75) -> (-20.7289, -8.75)
  line L18 (-22.5, 8.75) -> (-22.5, -8.75)
  line L19 (-20.7289, 8.75) -> (-22.5, 8.75)
  line L20 (-2.325, 34.125) -> (-2.325, 29.875)
  line L21 (2.325, 34.125) -> (-2.325, 34.125)
  line L22 (2.325, 29.875) -> (2.325, 34.125)
  line L23 (2.3746, 28.5229) -> (2.325, 29.875)
  line L24 (-2.325, 29.875) -> (-2.3746, 28.5229)
  line L25 (-1.75, 27.875) -> (1.75, 27.875)
  circle C1 centre (7.325, 17.5) radius 2
  circle C2 centre (7.325, -17.5) radius 2
  circle C3 centre (7.325, 17.5) radius 1.4
  circle C4 centre (7.325, -17.5) radius 1.4
  arc A1 centre (29.1716, -39.2776) radius 2 clockwise from (30.5858, -40.6918) to (29.1716, -41.2776)
  arc A2 centre (39.2776, -29.1716) radius 2 clockwise from (41.2776, -29.1716) to (40.6918, -30.5858)
  arc A3 centre (39.2776, 29.1716) radius 2 clockwise from (40.6918, 30.5858) to (41.2776, 29.1716)
  arc A4 centre (29.1716, 39.2776) radius 2 clockwise from (29.1716, 41.2776) to (30.5858, 40.6918)
  arc A5 centre (24.1231, 36.3855) radius 5.08 clockwise from (24.1231, 41.4655) to (25.492, 41.2776)
  arc A6 centre (-24.1331, 36.3855) radius 5.08 clockwise from (-25.502, 41.2776) to (-24.1331, 41.4655)
  arc A7 centre (-29.1716, 39.2776) radius 2 clockwise from (-30.5858, 40.6918) to (-29.1716, 41.2776)
  arc A8 centre (-39.2776, 29.1716) radius 2 clockwise from (-41.2776, 29.1716) to (-40.6918, 30.5858)
  arc A9 centre (-39.2776, -29.1716) radius 2 clockwise from (-40.6918, -30.5858) to (-41.2776, -29.1716)
  arc A10 centre (-29.1716, -39.2776) radius 2 clockwise from (-29.1716, -41.2776) to (-30.5858, -40.6918)
  circle C5 centre (36.96, 18.76) radius 1.4
  circle C6 centre (18.76, -36.96) radius 1.4
  circle C7 centre (-36.96, 18.76) radius 1.4
  circle C8 centre (-18.76, 36.96) radius 1.4
  circle C9 centre (-36.96, -18.76) radius 1.4
  circle C10 centre (-18.76, -36.96) radius 1.4
  circle C11 centre (36.96, -18.76) radius 1.4
  circle C12 centre (18.76, 36.96) radius 1.4
  circle C13 centre (31.4309, 31.4309) radius 2.159
  circle C14 centre (31.4309, -31.4309) radius 2.159
  circle C15 centre (-31.4309, 31.4309) radius 2.159
  circle C16 centre (-31.4309, -31.4309) radius 2.159
  arc A11 centre (0, 0) radius 22.5 clockwise from (-20.7289, 8.75) to (0, 22.5)
  arc A12 centre (0, 0) radius 15 clockwise from (0, -15) to (0, 15)
  circle C17 centre (0, 0) radius 5
  arc A13 centre (0, 0) radius 22.5 clockwise from (0, -22.5) to (-20.7289, -8.75)
  arc A14 centre (1.75, 28.5) radius 0.625 clockwise from (2.3746, 28.5229) to (1.75, 27.875)
  arc A15 centre (-1.75, 28.5) radius 0.625 clockwise from (-1.75, 27.875) to (-2.3746, 28.5229)
  point P3 (0, -38.2776)
  point P2 (-7.5, -41.2776)
  point P6 (7.5, -41.2776)
  point P1 (0, 0)
  coincident P3 L2
  symmetric P2 L2 P6
  concentric C1 C3
  concentric C2 C4
  equal C3 C4
  vertical L2
  vertical P1 P3
  coincident P6 L14
  dimension "d337" diameter C3 = 2.8
  dimension "d376" distance P2 P6 = 15
  dimension "d415" distance P3 L4 = 3
extrude "Extrude2" add sketch "Lil Microswitch zero nub" profile of L1 L3 L4 L14 along normal blind 12
sketch "Sketch3" plane through (0, 62, 0) normal (0, -1, 0) x axis (1, 0, 0)
  line L1 (-64.3937, -16.25) -> (64.3937, -16.25)
  line L2 (-64.3937, 16.25) -> (-64.3937, -16.25)
  line L3 (64.3937, 16.25) -> (-64.3937, 16.25)
  line L4 (64.3937, -16.25) -> (64.3937, 16.25)
  line L5 (-64.3937, 16.25) -> (64.3937, -16.25)
  line L6 (64.3937, 16.25) -> (-64.3937, -16.25)
  line L7 (-16.25, -80.1982) -> (16.25, -80.1982)
  line L8 (-16.25, 80.1982) -> (-16.25, -80.1982)
  line L9 (16.25, 80.1982) -> (-16.25, 80.1982)
  line L10 (16.25, -80.1982) -> (16.25, 80.1982)
  line L11 (-16.25, 80.1982) -> (16.25, -80.1982)
  line L12 (16.25, 80.1982) -> (-16.25, -80.1982)
  line L13 (29.1716, -41.2776) -> (-29.1716, -41.2776)
  line L14 (40.6918, -30.5858) -> (30.5858, -40.6918)
  line L15 (41.2776, 29.1716) -> (41.2776, -29.1716)
  line L16 (30.5858, 40.6918) -> (40.6918, 30.5858)
  line L17 (25.492, 41.2776) -> (29.1716, 41.2776)
  line L18 (-24.1331, 41.4655) -> (24.1231, 41.4655)
  line L19 (-29.1716, 41.2776) -> (-25.502, 41.2776)
  line L20 (-40.6918, 30.5858) -> (-30.5858, 40.6918)
  line L21 (-41.2776, -29.1716) -> (-41.2776, 29.1716)
  line L22 (-30.5858, -40.6918) -> (-40.6918, -30.5858)
  line L23 (0, 15) -> (0, 22.5)
  line L24 (0, -22.5) -> (0, -15)
  line L25 (-22.5, -8.75) -> (-20.7289, -8.75)
  line L26 (-22.5, 8.75) -> (-22.5, -8.75)
  line L27 (-20.7289, 8.75) -> (-22.5, 8.75)
  line L28 (-2.325, 34.125) -> (-2.325, 29.875)
  line L29 (2.325, 34.125) -> (-2.325, 34.125)
  line L30 (2.325, 29.875) -> (2.325, 34.125)
  line L31 (-2.325, 29.875) -> (-2.3746, 28.5229)
  line L32 (2.3746, 28.5229) -> (2.325, 29.875)
  line L33 (-1.75, 27.875) -> (1.75, 27.875)
  circle C1 centre (0, 0) radius 41.6095
  arc A1 centre (29.1716, -39.2776) radius 2 clockwise from (30.5858, -40.6918) to (29.1716, -41.2776)
  arc A2 centre (39.2776, -29.1716) radius 2 clockwise from (41.2776, -29.1716) to (40.6918, -30.5858)
  arc A3 centre (39.2776, 29.1716) radius 2 clockwise from (40.6918, 30.5858) to (41.2776, 29.1716)
  arc A4 centre (29.1716, 39.2776) radius 2 clockwise from (29.1716, 41.2776) to (30.5858, 40.6918)
  arc A5 centre (24.1231, 36.3855) radius 5.08 clockwise from (24.1231, 41.4655) to (25.492, 41.2776)
  arc A6 centre (-24.1331, 36.3855) radius 5.08 clockwise from (-25.502, 41.2776) to (-24.1331, 41.4655)
  arc A7 centre (-29.1716, 39.2776) radius 2 clockwise from (-30.5858, 40.6918) to (-29.1716, 41.2776)
  arc A8 centre (-39.2776, 29.1716) radius 2 clockwise from (-41.2776, 29.1716) to (-40.6918, 30.5858)
  arc A9 centre (-39.2776, -29.1716) radius 2 clockwise from (-40.6918, -30.5858) to (-41.2776, -29.1716)
  arc A10 centre (-29.1716, -39.2776) radius 2 clockwise from (-29.1716, -41.2776) to (-30.5858, -40.6918)
  circle C2 centre (-31.4309, 31.4309) radius 2.159
  circle C3 centre (31.4309, -31.4309) radius 2.159
  arc A11 centre (0, 0) radius 22.5 clockwise from (-20.7289, 8.75) to (0, 22.5)
  arc A12 centre (0, 0) radius 15 clockwise from (0, -15) to (0, 15)
  arc A13 centre (0, 0) radius 22.5 clockwise from (0, -22.5) to (-20.7289, -8.75)
  circle C4 centre (36.96, -18.76) radius 1.4
  circle C5 centre (18.76, 36.96) radius 1.4
  circle C6 centre (-18.76, -36.96) radius 1.4
  circle C7 centre (-31.4309, -31.4309) radius 2.159
  circle C8 centre (0, 0) radius 5
  circle C9 centre (36.96, 18.76) radius 1.4
  circle C10 centre (18.76, -36.96) radius 1.4
  circle C11 centre (-36.96, -18.76) radius 1.4
  circle C12 centre (-18.76, 36.96) radius 1.4
  circle C13 centre (-36.96, 18.76) radius 1.4
  circle C14 centre (31.4309, 31.4309) radius 2.159
  arc A14 centre (1.75, 28.5) radius 0.625 clockwise from (2.3746, 28.5229) to (1.75, 27.875)
  arc A15 centre (-1.75, 28.5) radius 0.625 clockwise from (-1.75, 27.875) to (-2.3746, 28.5229)
  point P1 (0, 0)
  point P2 (0, 0)
  point P7 (0, 0)
  point P12 (0, 0)
  point P4 (-64.3937, -16.25)
  point P5 (-64.3937, 16.25)
  point P10 (-16.25, 80.1982)
  point P11 (16.25, 80.1982)
  coincident P1 P2
  horizontal L1
  perpendicular L1 L2
  parallel L1 L3
  parallel L2 L4
  coincident L5 P7
  coincident L6 P7
  coincident P1 P7
  horizontal L7
  perpendicular L7 L8
  parallel L7 L9
  parallel L8 L10
  coincident L11 P12
  coincident L12 P12
  coincident P7 P12
  dimension "d202" distance P4 P5 = 32.5 (= "d203")
  dimension "d203" distance P10 P11 = 32.5
extrude "Extrude3" add sketch "Sketch3" profile of C1 L1 L3 L8 L10 L13 A1 L14 A2 L15 A3 L16 A4 L17 A5 L18 A6 L19 A7 L20 A8 L21 A9 L22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 to an object
sketch "Trace for Decal" plane through (0, 2.5, 0) normal (0, -1, 0) x axis (1, 0, 0)
  circle C1 centre (0, 0) radius 27.6721
  circle C2 centre (0, 0) radius 37.25
extrude "Extrude8" cut of existing geometry blind -1
sketch "Sketch2" plane through (0, -4.75, 0) normal (0, 1, 0) x axis (-1, 0, 0)
  line L1 (14.134, 33.6806) -> (14.9494, 36.7238)
  line L2 (0, 37.4678) -> (14.134, 33.6806)
  line L3 (-14.134, 33.6806) -> (0, 37.4678)
  line L4 (-14.9494, 36.7238) -> (-14.134, 33.6806)
  line L5 (-26.4198, -23.75) -> (-26.6164, -23.75)
  line L6 (26.6164, -23.75) -> (26.4198, -23.75)
  line L7 (-1.5, -41.2776) -> (-1.5, -39.6216)
  line L8 (1.5, -39.6216) -> (1.5, -41.2776)
  line L9 (1.5, -41.2776) -> (-1.5, -41.2776)
  arc A1 centre (0, 0) radius 39.65 clockwise from (-1.5, -39.6216) to (-15.15, 36.6415)
  arc A2 centre (0, 0) radius 39.65 clockwise from (14.9494, 36.7238) to (15.15, 36.6415)
  circle C1 centre (0, 0) radius 39.65
  arc A3 centre (0, 0) radius 35.5256 clockwise from (-26.4198, -23.75) to (26.4198, -23.75)
  arc A4 centre (0, 0) radius 35.6721 clockwise from (26.6164, -23.75) to (-26.6164, -23.75)
  arc A5 centre (0, 0) radius 39.65 clockwise from (15.15, 36.6415) to (1.5, -39.6216)
  arc A6 centre (0, 0) radius 39.65 clockwise from (-15.15, 36.6415) to (-14.9494, 36.7238)
extrude "Extrude2" cut sketch "Sketch2" profile of A1 A2 L1 L2 L3 L4 C1 L5 A3 L6 A4 A5 A6 blind -2 Side2Offset 0
joint "Assemble2" alignAngle 0 alignOffsetX 0 alignOffsetY 0 alignOffsetZ 0
sketch "Sketch2" plane through (0, -1.75, 0) normal (0, -1, 0) x axis (1, 0, 0)
  line L1 (-14.9494, 36.7238) -> (-14.1663, 33.8014)
  line L2 (-1.35, -41.3) -> (-1.35, -39.627)
  line L3 (1.35, -41.3) -> (-1.35, -41.3)
  line L4 (1.35, -39.627) -> (1.35, -41.3)
  line L5 (14.1663, 33.8014) -> (14.9494, 36.7238)
  arc A1 centre (0, 0) radius 39.65 clockwise from (-1.35, -39.627) to (-14.9494, 36.7238)
  arc A2 centre (0, 0) radius 39.65 clockwise from (14.9494, 36.7238) to (1.35, -39.627)
  arc A3 centre (0, 0) radius 36.65 clockwise from (14.1663, 33.8014) to (-14.1663, 33.8014)
  circle C1 centre (0, 0) radius 39.65
  point P9 (14.9494, 36.7238)
  concentric A1 C1
  coincident P9 C1
extrude "Extrude2" cut of existing geometry to an object
work_plane "WorkPlane1" AlongDistance 0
